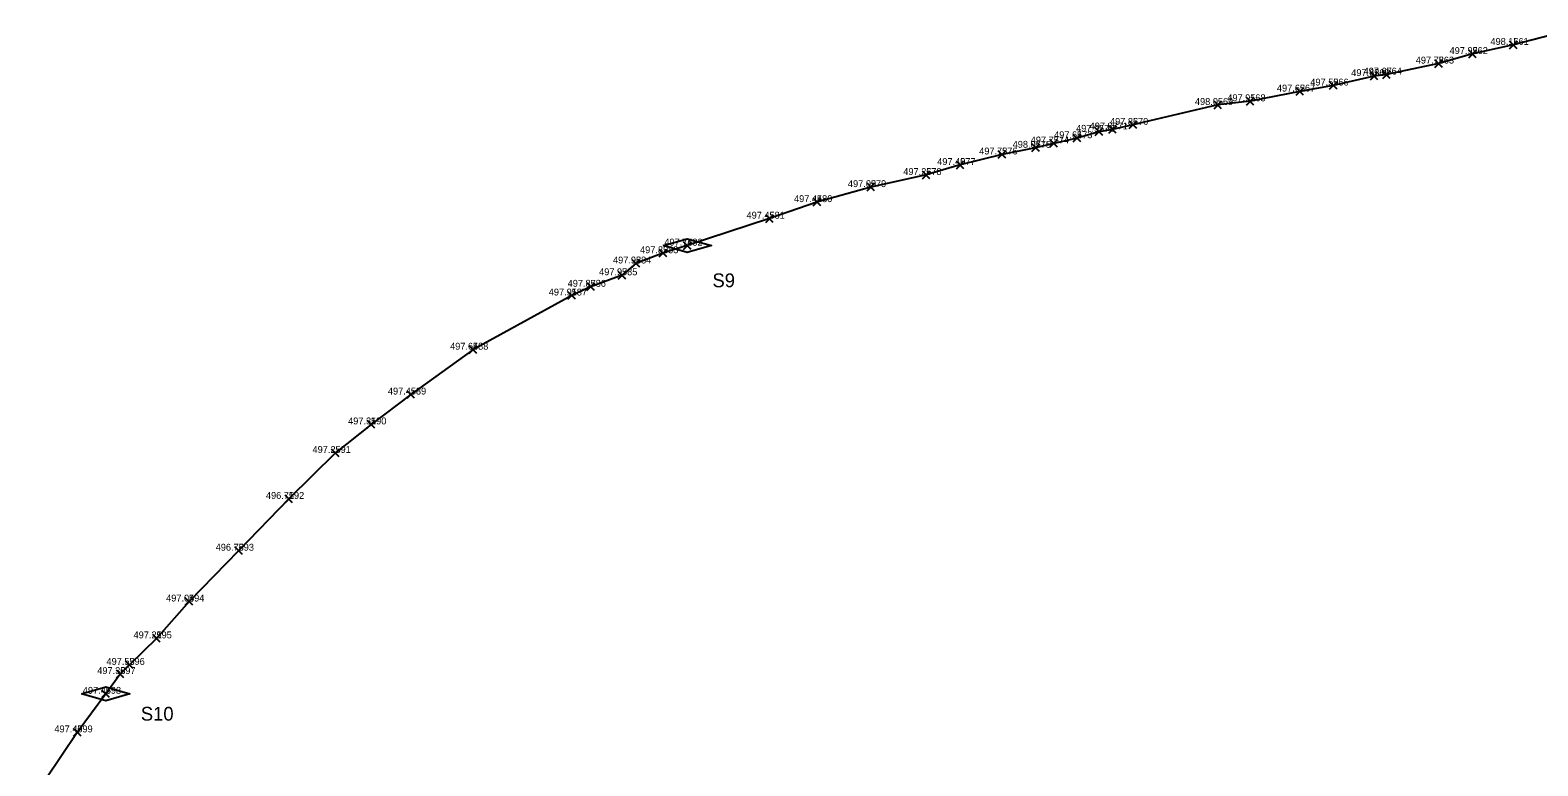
# Model space of a CAD drawing. Extents: x -874041 to -866452, y -1055592 to -1049889.
# Drawn here: x -868083.1 to -867864, y -1053626.2 to -1053519.4 of the extents above; entities that cross this region are included whole.
import ezdxf

# ---------------------------------------------------------------- set-up
doc = ezdxf.new("R2010")
doc.units = 0
for name, color, linetype in [('Vrstva 32', 7, 'Continuous'), ('Vrstva 60', 7, 'Continuous'), ('Vrstva 61', 7, 'Continuous')]:
    doc.layers.add(name, color=color, linetype=linetype)

msp = doc.modelspace()

# ---------------------------------------------------------------- linework, layer by layer
at = {"layer": 'Vrstva 32'}
for points in [[(-867859.34, -1053519.36), (-867867.59, -1053521.5), (-867873.53, -1053522.82), (-867878.44, -1053524.21), (-867886.02, -1053525.81), (-867887.81, -1053526.03), (-867893.76, -1053527.4), (-867898.61, -1053528.27), (-867905.82, -1053529.68), (-867910.52, -1053530.22), (-867922.86, -1053533.11), (-867925.82, -1053533.78), (-867927.79, -1053534.11), (-867930.98, -1053535.05), (-867934.37, -1053535.81), (-867937, -1053536.44), (-867941.86, -1053537.41), (-867947.96, -1053538.94), (-867952.89, -1053540.39), (-867960.93, -1053542.15)], [(-867960.93, -1053542.15), (-867968.76, -1053544.33), (-867975.66, -1053546.73), (-867987.6, -1053550.64), (-867991.13, -1053551.75), (-867995.06, -1053553.24), (-867997.08, -1053554.95), (-868001.65, -1053556.62), (-868004.39, -1053557.89), (-868018.73, -1053565.76), (-868027.76, -1053572.27), (-868033.54, -1053576.61), (-868038.71, -1053580.75), (-868045.48, -1053587.43), (-868052.78, -1053594.95), (-868059.98, -1053602.33), (-868064.71, -1053607.68), (-868068.64, -1053611.53)], [(-867991.1, -1053550.64), (-867987.6, -1053549.64), (-867984.1, -1053550.64), (-867987.6, -1053551.64), (-867991.1, -1053550.64)], [(-868068.64, -1053611.53), (-868069.98, -1053612.86), (-868072.08, -1053615.73), (-868076.21, -1053621.33), (-868083.06, -1053631.52)], [(-868075.58, -1053615.73), (-868072.08, -1053614.73), (-868068.58, -1053615.73), (-868072.08, -1053616.73), (-868075.58, -1053615.73)]]:
    msp.add_lwpolyline(points, dxfattribs=at)
at = {"layer": 'Vrstva 60'}
for p, q in [((-867868.14, -1053522.05), (-867867.04, -1053520.95)), ((-867867.04, -1053522.05), (-867868.14, -1053520.95)), ((-867878.99, -1053524.76), (-867877.89, -1053523.66)), ((-867877.89, -1053524.76), (-867878.99, -1053523.66)), ((-867874.08, -1053523.37), (-867872.98, -1053522.27)), ((-867872.98, -1053523.37), (-867874.08, -1053522.27)), ((-867888.36, -1053526.58), (-867887.26, -1053525.48)), ((-867887.26, -1053526.58), (-867888.36, -1053525.48)), ((-867886.57, -1053526.36), (-867885.47, -1053525.26)), ((-867885.47, -1053526.36), (-867886.57, -1053525.26)), ((-867899.16, -1053528.82), (-867898.06, -1053527.72)), ((-867898.06, -1053528.82), (-867899.16, -1053527.72)), ((-867894.31, -1053527.95), (-867893.21, -1053526.85)), ((-867893.21, -1053527.95), (-867894.31, -1053526.85)), ((-867911.07, -1053530.77), (-867909.97, -1053529.67)), ((-867909.97, -1053530.77), (-867911.07, -1053529.67)), ((-867906.37, -1053530.23), (-867905.27, -1053529.13)), ((-867905.27, -1053530.23), (-867906.37, -1053529.13)), ((-867923.41, -1053533.66), (-867922.31, -1053532.56)), ((-867922.31, -1053533.66), (-867923.41, -1053532.56)), ((-867934.92, -1053536.36), (-867933.82, -1053535.26)), ((-867933.82, -1053536.36), (-867934.92, -1053535.26)), ((-867931.53, -1053535.6), (-867930.43, -1053534.5)), ((-867930.43, -1053535.6), (-867931.53, -1053534.5)), ((-867928.34, -1053534.66), (-867927.24, -1053533.56)), ((-867927.24, -1053534.66), (-867928.34, -1053533.56)), ((-867926.37, -1053534.33), (-867925.27, -1053533.23)), ((-867925.27, -1053534.33), (-867926.37, -1053533.23)), ((-867942.41, -1053537.96), (-867941.31, -1053536.86)), ((-867941.31, -1053537.96), (-867942.41, -1053536.86)), ((-867937.55, -1053536.99), (-867936.45, -1053535.89)), ((-867936.45, -1053536.99), (-867937.55, -1053535.89)), ((-867948.51, -1053539.49), (-867947.41, -1053538.39)), ((-867947.41, -1053539.49), (-867948.51, -1053538.39)), ((-867961.48, -1053542.7), (-867960.38, -1053541.6)), ((-867960.38, -1053542.7), (-867961.48, -1053541.6)), ((-867953.44, -1053540.94), (-867952.34, -1053539.84)), ((-867952.34, -1053540.94), (-867953.44, -1053539.84)), ((-867969.31, -1053544.88), (-867968.21, -1053543.78)), ((-867968.21, -1053544.88), (-867969.31, -1053543.78)), ((-867976.21, -1053547.28), (-867975.11, -1053546.18)), ((-867975.11, -1053547.28), (-867976.21, -1053546.18)), ((-867988.15, -1053551.19), (-867987.05, -1053550.09)), ((-867987.05, -1053551.19), (-867988.15, -1053550.09)), ((-867995.61, -1053553.79), (-867994.51, -1053552.69)), ((-867994.51, -1053553.79), (-867995.61, -1053552.69)), ((-867991.68, -1053552.3), (-867990.58, -1053551.2)), ((-867990.58, -1053552.3), (-867991.68, -1053551.2)), ((-867997.63, -1053555.5), (-867996.53, -1053554.4)), ((-867996.53, -1053555.5), (-867997.63, -1053554.4)), ((-868002.2, -1053557.17), (-868001.1, -1053556.07)), ((-868001.1, -1053557.17), (-868002.2, -1053556.07)), ((-868004.94, -1053558.44), (-868003.84, -1053557.34)), ((-868003.84, -1053558.44), (-868004.94, -1053557.34)), ((-868019.28, -1053566.31), (-868018.18, -1053565.21)), ((-868018.18, -1053566.31), (-868019.28, -1053565.21)), ((-868028.31, -1053572.82), (-868027.21, -1053571.72)), ((-868027.21, -1053572.82), (-868028.31, -1053571.72)), ((-868034.09, -1053577.16), (-868032.99, -1053576.06)), ((-868032.99, -1053577.16), (-868034.09, -1053576.06)), ((-868039.26, -1053581.3), (-868038.16, -1053580.2)), ((-868038.16, -1053581.3), (-868039.26, -1053580.2)), ((-868046.03, -1053587.98), (-868044.93, -1053586.88)), ((-868044.93, -1053587.98), (-868046.03, -1053586.88)), ((-868053.33, -1053595.5), (-868052.23, -1053594.4)), ((-868052.23, -1053595.5), (-868053.33, -1053594.4)), ((-868060.53, -1053602.88), (-868059.43, -1053601.78)), ((-868059.43, -1053602.88), (-868060.53, -1053601.78)), ((-868065.26, -1053608.23), (-868064.16, -1053607.13)), ((-868064.16, -1053608.23), (-868065.26, -1053607.13)), ((-868069.19, -1053612.08), (-868068.09, -1053610.98)), ((-868068.09, -1053612.08), (-868069.19, -1053610.98)), ((-868070.53, -1053613.41), (-868069.43, -1053612.31)), ((-868069.43, -1053613.41), (-868070.53, -1053612.31)), ((-868072.63, -1053616.28), (-868071.53, -1053615.18)), ((-868071.53, -1053616.28), (-868072.63, -1053615.18)), ((-868076.76, -1053621.88), (-868075.66, -1053620.78)), ((-868075.66, -1053621.88), (-868076.76, -1053620.78))]:
    msp.add_line(p, q, dxfattribs=at)

# ---------------------------------------------------------------- texts
at = {"layer": 'Vrstva 32'}
for s, p in [('S9', (-867983.94, -1053556.69)), ('S10', (-868066.98, -1053619.63))]:
    msp.add_text(s, height=2, dxfattribs=at).set_placement(p)
at = {"layer": 'Vrstva 60'}
for s, p in [('562', (-867873.53, -1053522.82)), ('561', (-867867.59, -1053521.5)), ('563', (-867878.44, -1053524.21)), ('566', (-867893.76, -1053527.4)), ('565', (-867887.81, -1053526.03)), ('564', (-867886.02, -1053525.81)), ('568', (-867905.82, -1053529.68)), ('567', (-867898.61, -1053528.27)), ('569', (-867910.52, -1053530.22)), ('572', (-867927.79, -1053534.11)), ('571', (-867925.82, -1053533.78)), ('570', (-867922.86, -1053533.11)), ('574', (-867934.37, -1053535.81)), ('573', (-867930.98, -1053535.05)), ('576', (-867941.86, -1053537.41)), ('575', (-867937, -1053536.44)), ('578', (-867952.89, -1053540.39)), ('577', (-867947.96, -1053538.94)), ('579', (-867960.93, -1053542.15)), ('580', (-867968.76, -1053544.33)), ('581', (-867975.66, -1053546.73)), ('583', (-867991.13, -1053551.75)), ('582', (-867987.6, -1053550.64)), ('584', (-867995.06, -1053553.24)), ('585', (-867997.08, -1053554.95)), ('587', (-868004.39, -1053557.89)), ('586', (-868001.65, -1053556.62)), ('588', (-868018.73, -1053565.76)), ('589', (-868027.76, -1053572.27)), ('590', (-868033.54, -1053576.61)), ('591', (-868038.71, -1053580.75)), ('592', (-868045.48, -1053587.43)), ('593', (-868052.78, -1053594.95)), ('594', (-868059.98, -1053602.33)), ('595', (-868064.71, -1053607.68)), ('597', (-868069.98, -1053612.86)), ('596', (-868068.64, -1053611.53)), ('598', (-868072.08, -1053615.73)), ('599', (-868076.21, -1053621.33))]:
    msp.add_text(s, height=1, dxfattribs=at).set_placement(p)
at = {"layer": 'Vrstva 61'}
for s, p in [('497.92 ', (-867876.86, -1053522.82)), ('498.16 ', (-867870.92, -1053521.5)), ('497.78 ', (-867881.77, -1053524.21)), ('497.59 ', (-867897.09, -1053527.4)), ('497.63 ', (-867891.14, -1053526.03)), ('497.67 ', (-867889.35, -1053525.81)), ('497.91 ', (-867909.15, -1053529.68)), ('497.62 ', (-867901.94, -1053528.27)), ('498.05 ', (-867913.85, -1053530.22)), ('497.95 ', (-867931.12, -1053534.11)), ('497.87 ', (-867929.15, -1053533.78)), ('497.86 ', (-867926.19, -1053533.11)), ('497.77 ', (-867937.7, -1053535.81)), ('497.64 ', (-867934.31, -1053535.05)), ('497.72 ', (-867945.19, -1053537.41)), ('498.05 ', (-867940.33, -1053536.44)), ('497.26 ', (-867956.22, -1053540.39)), ('497.40 ', (-867951.29, -1053538.94)), ('497.09 ', (-867964.26, -1053542.15)), ('497.44 ', (-867972.09, -1053544.33)), ('497.45 ', (-867978.99, -1053546.73)), ('497.89 ', (-867994.46, -1053551.75)), ('497.74 ', (-867990.93, -1053550.64)), ('497.98 ', (-867998.39, -1053553.24)), ('497.97 ', (-868000.41, -1053554.95)), ('497.91 ', (-868007.72, -1053557.89)), ('497.87 ', (-868004.98, -1053556.62)), ('497.64 ', (-868022.06, -1053565.76)), ('497.45 ', (-868031.09, -1053572.27)), ('497.31 ', (-868036.87, -1053576.61)), ('497.25 ', (-868042.04, -1053580.75)), ('496.71 ', (-868048.81, -1053587.43)), ('496.78 ', (-868056.11, -1053594.95)), ('497.04 ', (-868063.31, -1053602.33)), ('497.21 ', (-868068.04, -1053607.68)), ('497.38 ', (-868073.31, -1053612.86)), ('497.53 ', (-868071.97, -1053611.53)), ('497.45 ', (-868075.41, -1053615.73)), ('497.40 ', (-868079.54, -1053621.33))]:
    msp.add_text(s, height=1, dxfattribs=at).set_placement(p)

doc.saveas('drawing.dxf')
